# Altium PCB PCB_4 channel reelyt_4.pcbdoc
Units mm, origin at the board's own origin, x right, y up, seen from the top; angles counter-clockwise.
Board outline 162.7 x 82.93 mm, 2 copper layers (Top Layer, Bottom Layer); 40 components, 54 nets, 169 pads, 1 vias.
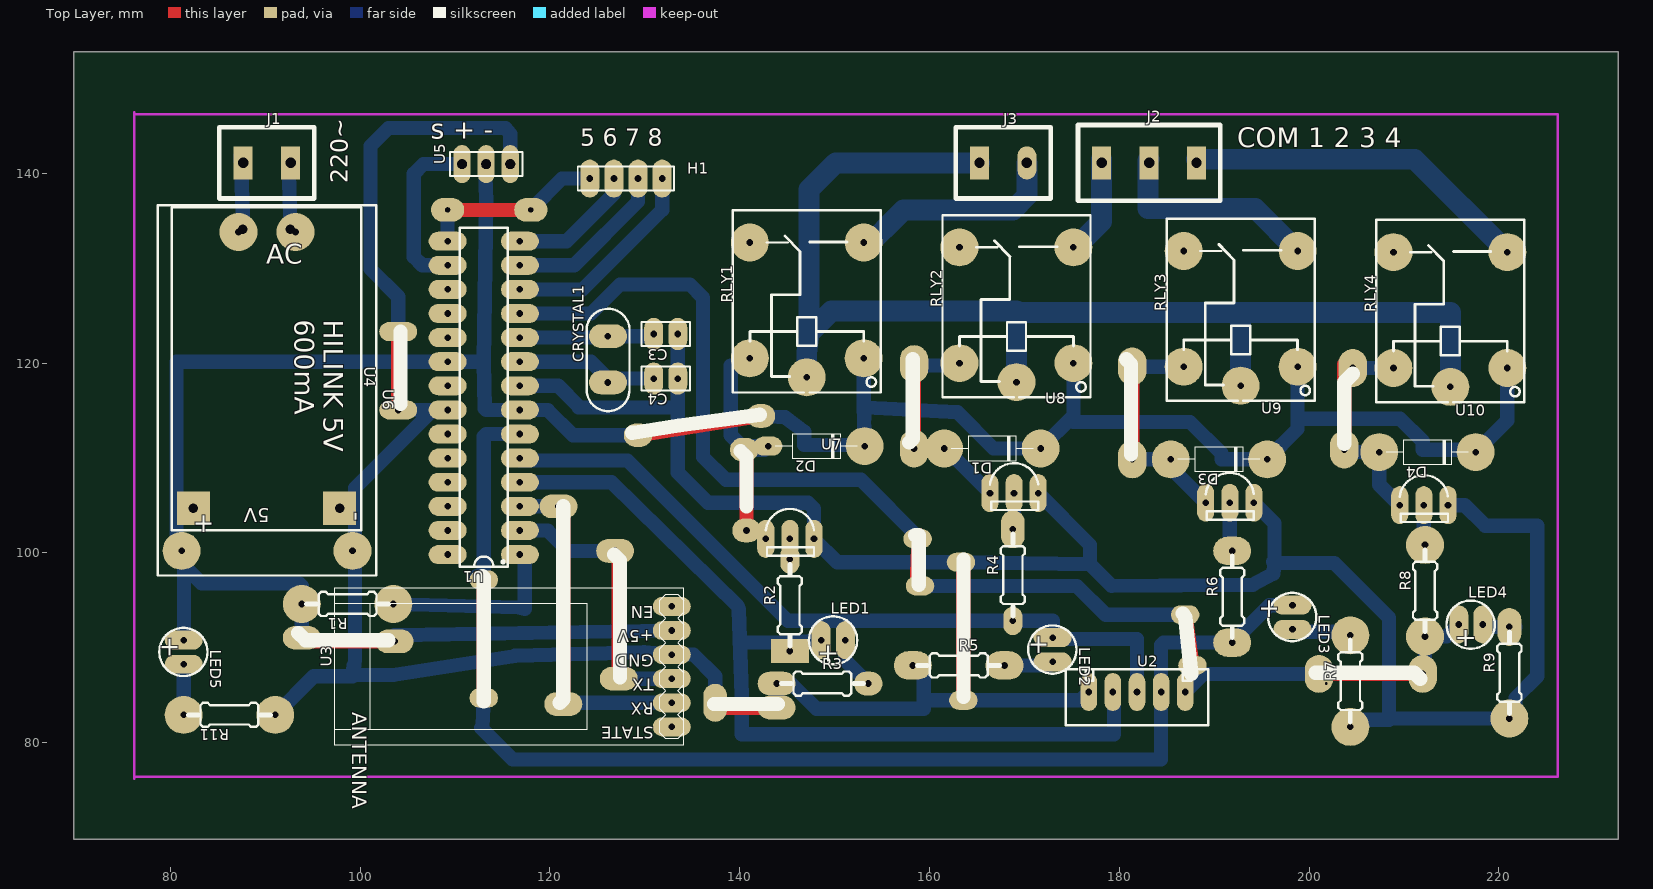
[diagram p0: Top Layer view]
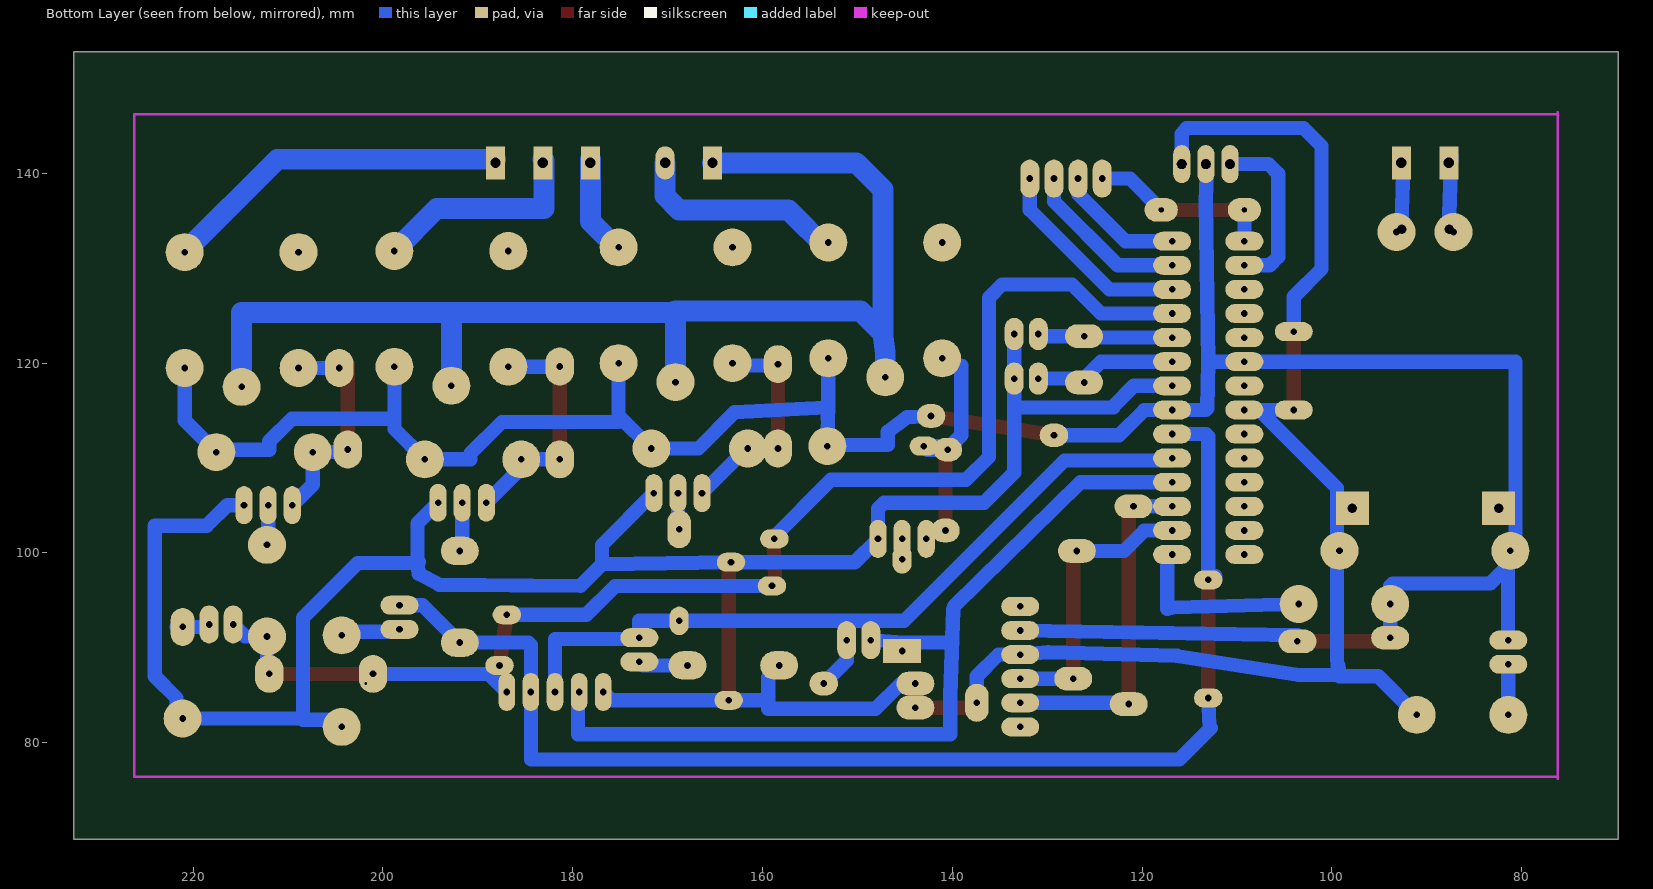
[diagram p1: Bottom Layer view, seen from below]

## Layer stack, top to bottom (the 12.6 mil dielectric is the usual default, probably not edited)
Top Layer: signal copper (thickness not stored)
Dielectric: dielectric 0.32, FR-4, Dk 4.8
Bottom Layer: signal copper (thickness not stored)

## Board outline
232.55,69.85 69.85,69.85 69.85,152.781 232.55,152.781

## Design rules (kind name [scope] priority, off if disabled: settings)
BoardOutlineClearance Default [All] p0: genericclearance=0.254 ignorepadtopadclearanceinfootprint=FALSE except(0: Region-CutoutEdge Arc-SplitContinuation Track-SplitContinuation SMDPad-SplitContinuation THPad-SplitContinuation Via-SplitContinuation Fill-SplitContinuation Poly-SplitContinuation Region-SplitContinuation Text-SplitContinuation; 0.399: Track-OutlineEdge SMDPad-OutlineEdge THPad-OutlineEdge Via-OutlineEdge Fill-OutlineEdge Region-OutlineEdge Poly-OutlineEdge Text-OutlineEdge Sheet-OutlineEdge Hole-OutlineEdge Track-CutoutEdge SMDPad-CutoutEdge THPad-CutoutEdge Via-CutoutEdge Fill-CutoutEdge Poly-CutoutEdge Text-CutoutEdge Sheet-CutoutEdge Hole-CutoutEdge)
Clearance Default [All] p1: gap=0.178 ignorepadtopadclearanceinfootprint=FALSE except(0: Region-Region; 0.399: Track-Track SMDPad-Track THPad-Track Via-Track Fill-Track Region-Track Poly-Track Text-Track Sheet-Track Hole-Track Track-SMDPad SMDPad-SMDPad THPad-SMDPad Via-SMDPad Fill-SMDPad Region-SMDPad Poly-SMDPad Text-SMDPad Sheet-SMDPad Hole-SMDPad Track-THPad SMDPad-THPad THPad-THPad Via-THPad Fill-THPad Region-THPad Poly-THPad Text-THPad Sheet-THPad Hole-THPad Track-Via SMDPad-Via THPad-Via Via-Via Fill-Via Region-Via Poly-Via Text-Via Sheet-Via Hole-Via Track-Fill SMDPad-Fill THPad-Fill Via-Fill Fill-Fill Region-Fill Poly-Fill Text-Fill Sheet-Fill Hole-Fill Track-Region SMDPad-Region THPad-Region Via-Region Fill-Region Poly-Region Text-Region Sheet-Region Hole-Region Track-Poly SMDPad-Poly THPad-Poly Via-Poly Fill-Poly Region-Poly Poly-Poly Text-Poly Sheet-Poly Hole-Poly Track-Text SMDPad-Text THPad-Text Via-Text Fill-Text Region-Text Poly-Text Text-Text Sheet-Text Hole-Text Track-Sheet SMDPad-Sheet THPad-Sheet Via-Sheet Fill-Sheet Region-Sheet Poly-Sheet Text-Sheet Sheet-Sheet Hole-Sheet Track-Hole SMDPad-Hole THPad-Hole Via-Hole Fill-Hole Region-Hole Poly-Hole Text-Hole Sheet-Hole Hole-Hole)
PasteMaskExpansion Common [All] p1: expansion=0
PlaneConnect Default [All] p1: planeconnectstyle=Relief reliefexpansion=0.508 reliefentries=4 reliefconductorwidth=0 reliefairgap=0.025
PolygonConnect Default [All] p1: connectstyle=Relief reliefentries=4 reliefconductorwidth=0 polygonreliefangle="90 Angle" airgapwidth=10
RoutingVias Default [All] p1: viastyle="Through Hole" holewidth=12.008000000000001 minholewidth=12.008000000000001 maxholewidth=2362 width=24.016000000000002 minwidth=24.016000000000002 maxwidth=3938
SolderMaskExpansion Common [All] p1: useseparateexpansions=TRUE expansion=2 expansionbottom=2
Width Default [All] p1: maxlimit=1000 minlimit=59 preferedwidth=59

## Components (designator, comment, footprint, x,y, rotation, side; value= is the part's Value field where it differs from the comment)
C3 "22pf" CAP-TH_L5.0-W2.5-P2.54-D0.7 132.207,123.063 r180 top
C4 "22pf" CAP-TH_L5.0-W2.5-P2.54-D0.7 132.207,118.364 r180 top
CRYSTAL1 "mhz" CRYSTAL-TH_L10.8-W4.5-P4.88 126.111,120.396 r90 top
D1 "1N4007" 1N4007#1 166.624,110.998 r180 top
D2 "1N4007" 1N4007#2 148.082,111.252 r180 top
D3 "1N4007" 1N4007#1 190.5,109.855 r180 top
D4 "1N4007" 1N4007#1 212.471,110.617 r180 top
H1 "1X4 header" "HEADER - HEADER-FEMALE-2.54_1X4" 126.746,139.446 r0 top
J1 "2 X 5MM" "PCB MOUNT SCREW TERMINALS - 2 X 5MM"#1 90.17,141.097 r0 top
J2 "3 X 5MM terminal" "PCB MOUNT SCREW TERMINALS - 3 X 5MM" 183.134,141.097 r0 top
J3 "2 X 5MM" "PCB MOUNT SCREW TERMINALS - 2 X 5MM"#2 167.767,141.097 r0 top
LED1 "LED 5MM" LED-5MM-5MM 151.13,88.265 r0 top
LED2 "LED 5MM" LED-5MM-5MM 170.434,88.519 r270 top
LED3 "LED 5MM" LED-5MM-5MM 195.707,91.948 r270 top
LED4 "LED 5MM" LED-5MM-5MM 218.313,89.916 r0 top
LED5 "LED 5MM" LED-5MM-5MM 78.867,88.265 r270 top
R1 "10k" RESISTOR-1/4W#1 98.679,94.615 r180 top
R2 "100e" RESISTOR-1/4W#2 145.288,94.488 r90 top
R3 "220e" RESISTOR-1/4W#3 148.717,86.233 r0 top
R4 "100e" RESISTOR-1/4W#4 168.783,97.663 r90 top
R5 "220e" RESISTOR-1/4W#5 163.068,88.138 r0 top
R6 "100e" RESISTOR-1/4W#6 191.897,95.377 r90 top
R7 "220e" RESISTOR-1/4W#1 204.343,86.487 r90 top
R8 "100e" RESISTOR-1/4W#1 212.217,96.012 r90 top
R9 "220e" RESISTOR-1/4W#7 221.107,87.376 r90 top
R11 "220e" RESISTOR-1/4W#1 86.233,82.931 r180 top
RLY1 "Реле пылесоса 12В" RELAY-TH_SRD-XXVDC-XL-C 147.066,125.603 r90 top
RLY2 "Реле пылесоса 12В" RELAY-TH_SRD-XXVDC-XL-C 169.164,125.095 r90 top
RLY3 "Реле пылесоса 12В" RELAY-TH_SRD-XXVDC-XL-C 192.786,124.714 r90 top
RLY4 "Реле пылесоса 12В" RELAY-TH_SRD-XXVDC-XL-C 214.884,124.587 r90 top
U1 "ATMEGA328 DIP" ATMEGA328P 113.03,116.332 r180 top
U2 "HEADER5" CONN-TH_HEADER5 181.864,85.344 r0 top
U3 "AMG AMGProductions GTIL HC-05 Bluetooth-module" WIRELESS-BLUETOOTH-HC-05 132.842,84.201 r90 top
U4 "HILINK" HILINK 80.137,136.398 r270 top
U5 "HEADER FEMALE 2.54 1X3 COPY" "HEADER - HEADER-FEMALE-2.54_1X3" 110.744,140.97 r90 top
U6 "HILINK 5V corrected" FP_HILINK_5V_1A 91.694,136.017 r270 top
U7 "TRANSISTOR NPN TO-92 (BC548) COPY" "TRANSISTOR NPN TO-92 (BC548)" 145.288,102.235 r0 top
U8 "TRANSISTOR NPN TO-92 (BC548) COPY" "TRANSISTOR NPN TO-92 (BC548)" 168.91,107.061 r0 top
U9 "TRANSISTOR NPN TO-92 (BC548) COPY" "TRANSISTOR NPN TO-92 (BC548)" 191.643,106.045 r0 top
U10 "TRANSISTOR NPN TO-92 (BC548) COPY" "TRANSISTOR NPN TO-92 (BC548)" 212.09,105.791 r0 top

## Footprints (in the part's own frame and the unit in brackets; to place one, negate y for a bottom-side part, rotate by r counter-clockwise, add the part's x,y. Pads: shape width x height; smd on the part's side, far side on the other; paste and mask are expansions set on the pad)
1N4007#1 [mm]
  round 4 hole 0.7: A(5.08,0) K(-5.08,0)
  silkscreen extent -4.32,-1.27 4.32,1.27
1N4007#2 [mm]
  oval 3x2 hole 0.7: A(5.08,0)
  round 4 hole 0.7: K(-5.08,0)
  silkscreen extent -4.32,-1.27 4.32,1.27
ATMEGA328P [mm]
  oval 4x2 hole 0.7: 1(-3.81,16.51) 2(-3.81,13.97) 3(-3.81,11.43) 4(-3.81,8.89) 5(-3.81,6.35) 6(-3.81,3.81) 7(-3.81,1.27) 8(-3.81,-1.27) 9(-3.81,-3.81) 10(-3.81,-6.35) 11(-3.81,-8.89) 12(-3.81,-11.43) 13(-3.81,-13.97) 14(-3.81,-16.51) 15(3.81,-16.51) 16(3.81,-13.97) 17(3.81,-11.43) 18(3.81,-8.89) 19(3.81,-6.35) 20(3.81,-3.81) 21(3.81,-1.27) 22(3.81,1.27) 23(3.81,3.81) 24(3.81,6.35) 25(3.81,8.89) 26(3.81,11.43) 27(3.81,13.97) 28(3.81,16.51)
  silkscreen extent -2.54,-17.91 2.54,17.78
CAP-TH_L5.0-W2.5-P2.54-D0.7 [mm]
  oval 2x3.4 hole 0.7: 1(-1.27,0) 2(1.27,0)
  silkscreen extent -2.54,-1.27 2.54,1.27
CONN-TH_HEADER5 [mm]
  oval 1.75x4 hole 0.7: 1(-5.08,0) 2(-2.54,0) 3(0,0) 4(2.54,0) 5(5.08,0)
  silkscreen extent -7.5,-3.5 7.5,2.4
CRYSTAL-TH_L10.8-W4.5-P4.88 [mm]
  oval 2.5x4 hole 0.7: 1(-2.44,0) 2(2.44,0)
  silkscreen extent -5.46,-2.28 5.32,2.24
FP_HILINK_5V_1A [mm]
  round 4 hole 0.7: 1(2.2,1.501) 2(2.2,-4.501) 3(35.799,7.501) 4(35.799,-10.5)
  silkscreen extent -0.6,-13 38.4,10
"HEADER - HEADER-FEMALE-2.54_1X3" [mm]
  oval 4x1.8 hole 1.016 slot 1.021 at 0 deg: 1(0,0) 2(0,-2.54) 3(0,-5.08)
  silkscreen extent -1.27,-6.35 1.27,1.27
"HEADER - HEADER-FEMALE-2.54_1X4" [mm]
  oval 2x4 hole 0.7: 1(-2.54,0) 2(0,0) 3(2.54,0) 4(5.08,0)
  silkscreen extent -3.81,-1.27 6.35,1.27
HILINK [mm]
  round 2 hole 1: 1(2.3,12.5) 2(2.3,7.5)
  rect 3.5x3.5 hole 1: 3(31.7,17.7) 4(31.7,2.3)
  silkscreen extent 0,0 34,20
LED-5MM-5MM [mm]
  oval 2x4 hole 0.7: 1(-2.54,2.54) 2(0,2.54)
  silkscreen extent -3.83,-0.02 1.25,5.05
"PCB MOUNT SCREW TERMINALS - 2 X 5MM"#1 [mm]
  rect 2x3.5 hole 1.1: 1(-2.5,0) 2(2.5,0)
  silkscreen extent -5,-3.75 5,3.75
"PCB MOUNT SCREW TERMINALS - 2 X 5MM"#2 [mm]
  rect 2x3.5 hole 1.1: 1(-2.5,0)
  oval 2x3.5 hole 1.1: 2(2.5,0)
  silkscreen extent -5,-3.75 5,3.75
"PCB MOUNT SCREW TERMINALS - 3 X 5MM" [mm]
  rect 2x3.5 hole 1.1: 1(-5,0) 2(0,0) 3(5,0)
  silkscreen extent -7.5,-4 7.5,4
RELAY-TH_SRD-XXVDC-XL-C [mm]
  round 4 hole 0.7: 1(-5.1,-6) 2(7.1,-5.999) 3(7.1,5.999) 4(-5.1,6) 5(-7.1,0)
  silkscreen extent -8.7,-7.8 10.5,7.8
RESISTOR-1/4W#1 [mm]
  round 4 hole 0.7: 1(-4.826,0) 2(4.826,0)
  silkscreen extent -4.32,-1.27 4.32,1.27
RESISTOR-1/4W#2 [mm]
  rect 2.5x4 hole 0.7: 1(-4.826,0)
  oval 3x2 hole 0.7: 2(4.826,0)
  silkscreen extent -4.32,-1.27 4.32,1.27
RESISTOR-1/4W#3 [mm]
  oval 4x2.5 hole 0.7: 1(-4.826,0)
  oval 3x2.5 hole 0.7: 2(4.826,0)
  silkscreen extent -4.32,-1.27 4.32,1.27
RESISTOR-1/4W#4 [mm]
  oval 3x2 hole 0.7: 1(-4.826,0)
  oval 4x2.5 hole 0.7: 2(4.826,0)
  silkscreen extent -4.32,-1.27 4.32,1.27
RESISTOR-1/4W#5 [mm]
  oval 4x3 hole 0.7: 1(-4.826,0) 2(4.826,0)
  silkscreen extent -4.32,-1.27 4.32,1.27
RESISTOR-1/4W#6 [mm]
  oval 3x4 hole 0.7: 1(-4.826,0) 2(4.826,0)
  silkscreen extent -4.32,-1.27 4.32,1.27
RESISTOR-1/4W#7 [mm]
  round 4 hole 0.7: 1(-4.826,0)
  oval 4x2.5 hole 0.7: 2(4.826,0)
  silkscreen extent -4.32,-1.27 4.32,1.27
"TRANSISTOR NPN TO-92 (BC548)" [mm]
  oval 1.8x4 hole 0.7: 1(-2.54,-0.762) 2(0,-0.762) 3(2.54,-0.762)
  silkscreen extent -2.54,-2.54 2.54,2.39
WIRELESS-BLUETOOTH-HC-05 [mm]
  oval 2x4 hole 0.7: 1(-2.54,0) 2(0,0) 3(2.54,0) 4(5.08,0) 5(7.62,0) 6(10.16,0)
  silkscreen extent -4.45,-1.27 12.06,35.56

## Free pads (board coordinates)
  oval 4x2.5 hole 0.7: 2(126.873,100.203) 3(93.853,91.059) 3(127.254,86.741) 4(103.632,90.678) 4(143.891,83.693) 5(121.412,84.074) 6(120.904,104.902)
  oval 3x2 hole 0.7: 2(158.75,101.473) 3(159.004,96.52) 4(186.944,93.472) 5(187.706,88.138) 6(163.312,99.02) 7(163.563,84.468) 8(113.03,97.155) 10(113.03,84.709)
  oval 3x4 hole 0.7: 2(211.963,87.249) 4(201.041,87.249) 5(158.369,110.998) 6(158.369,119.888) 8(181.356,109.855) 10(204.597,119.487) 11(181.356,119.634) 12(203.708,110.891)
  oval 2.5x4 hole 0.7: 5(137.414,84.201)
  oval 3x2.5 hole 0.7: 5(140.462,110.871) 6(140.716,102.362) 7(129.286,112.395) 8(142.24,114.427)
  oval 4x2 hole 0.7: 6(104.013,123.317) 9(104.013,115.062)
  oval 3.5x2.5 hole 0.5 slot 0.525 at 0 deg: 13(109.22,136.144) 14(117.983,136.144)

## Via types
v1: diameter 0.62, hole 0.31, Top Layer to Bottom Layer, 1 vias

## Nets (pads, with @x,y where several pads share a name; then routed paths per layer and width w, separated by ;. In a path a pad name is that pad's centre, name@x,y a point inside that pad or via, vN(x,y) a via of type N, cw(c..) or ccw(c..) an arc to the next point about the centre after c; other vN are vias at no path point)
1: LED1.1 R2.1 U1.4 U2.2 | length 95.5
  Bottom Layer w1.5: U1.4 126.497,107.442 139.827,94.361 ; 139.893,94.056 140.208,84.963 140.208,80.899 179.451,80.899 179.451,85.217 U2.2 ; 140.144,90.551 R2.1@145.161,90.551 ; LED1.1 R2.1@145.161,90.551 ; R2.1@145.161,90.551 145.161,89.662 R2.1@145.161,90.551
2: LED2.1 R4.1 U1.5 U2.3 | length 79.4
  Bottom Layer w1.5: U1.5@116.84,109.728 128.189,109.728 143.937,93.98 145.08,92.837 R4.1 172.974,92.837 LED2.1 173.101,90.932 181.864,90.932 U2.3
3: LED3.1 pad.8@113.03,97.155 pad.10@113.03,84.709 R6.1 U1.6 U2.4 | length 136.5
  Top Layer w1.5: pad.10@113.03,84.709 pad.8@113.03,97.155
  Bottom Layer w1.5: pad.8@112.268,97.536 112.649,97.536 113.03,97.155 113.03,112.268 113.284,112.522 U1.6 ; pad.10@113.03,84.709 112.903,81.661 112.776,81.534 116.078,78.232 184.404,78.232 U2.4 ; U2.4@184.478,85.141 184.478,85.27 U2.4 ; LED3.1 195.834,94.488 R6.1 184.658,90.551 184.404,90.297 U2.4
4: LED4.1 pad.2@158.75,101.473 pad.2@211.963,87.249 pad.4@201.041,87.249 pad.5@187.706,88.138 R8.1 U1.11 U2.5 | length 112.6
  Top Layer w1.5: 158.623,96.456 pad.2@158.877,101.854 ; 186.944,93.472 pad.5@187.706,88.138 ; pad.4@201.041,87.249 pad.2@211.963,87.249
  Bottom Layer w1.5: U1.11@117.094,125.222 124.333,125.222 127.381,128.27 134.747,128.27 136.144,126.873 136.144,114.427 ; 136.144,115.062 136.144,110.109 138.557,107.696 152.781,107.696 pad.2@159.004,101.473 ; pad.5@187.706,88.138 187.706,86.106 U2.5 188.849,87.249 pad.4@201.041,87.249 ; pad.2@211.963,87.249 212.217,87.503 R8.1 214.503,91.186 LED4.1
  other v1: 201.803,86.233
+_1: U6.2 | length 8.1
  Bottom Layer w1.5: 87.416,141.859 87.681,134.051 U6.2@87.447,133.817
+_2: U6.1 | length 8.4
  Bottom Layer w1.5: 92.416,141.859 92.659,134.607 U6.1@93.449,133.817
CRYSTAL1_1: C4.2 CRYSTAL1.1 U1.9 | length 15.2
  Bottom Layer w1.5: U1.9 124.333,120.142 CRYSTAL1.1@126.111,118.364 ; CRYSTAL1.1 CRYSTAL1.1@126.111,118.364 ; C4.2 CRYSTAL1.1@126.111,118.364
CRYSTAL1_2: C3.2 CRYSTAL1.2 U1.10 | length 14.3
  Bottom Layer w1.5: U1.10 125.957,122.682 CRYSTAL1.2 130.71,122.836 C3.2
D2_A: D2.A pad.5@140.462,110.871 pad.6@140.716,102.362 RLY1.4 U7.1 | length 24.7
  Top Layer w1.5: pad.5@140.462,110.871 140.716,110.871 pad.6@140.716,102.87
  Bottom Layer w1.5: pad.5@140.462,110.871 142.621,110.871 D2.A 140.208,111.252 139.065,112.395 139.065,119.741 RLY1.4@141.067,119.741
GND: C3.1 C4.1 pad.4@143.891,83.693 pad.5@137.414,84.201 pad.6@104.013,123.317 pad.6@163.312,99.02 pad.7@163.563,84.468 pad.9 R3.1 R5.1 R7.1 R9.1 R11.1 U1.8 U1.22 U2.1 U3.4 U5.3 U6.3 U7.3 U8.3 U9.3 U10.3 | length 395.7
  Top Layer w1.5: pad.9 pad.6@104.013,123.317 ; pad.5@137.414,84.201 137.414,83.693 pad.4@143.891,83.693 ; pad.6@163.312,99.02 163.563,98.768 pad.7@163.563,84.468
  Bottom Layer w1.5: R11.1 95.123,86.995 99.187,86.995 ; 99.314,87.122 99.449,88.781 99.449,100.218 99.449,106.834 107.676,115.062 U1.22 104.775,115.062 pad.9 ; 99.314,88.138 99.187,87.122 103.505,87.122 116.332,89.154 129.921,89.535 U3.4 135.128,89.281 137.414,86.995 pad.5@137.414,84.201 ; pad.6@104.14,123.317 104.013,123.317 104.013,127 101.092,129.921 101.092,142.875 102.997,144.78 115.316,144.78 115.824,144.145 U5.3 ; U1.8 120.874,117.602 123.017,115.458 ; 123.016,115.316 133.477,115.316 ; C3.1 C4.1 133.477,108.458 136.652,105.283 147.193,105.283 147.828,104.648 U7.3 150.281,99.02 163.312,99.02 176.906,98.811 179.197,96.52 194.056,96.647 196.215,97.79 196.342,98.933 ; pad.4@143.891,83.693 R3.1 145.415,86.233 148.082,83.566 159.385,83.566 159.385,84.467 R5.1@159.385,86.868 ; 159.385,84.468 163.563,84.468 175.908,84.468 U2.1 ; U8.3 176.905,100.844 176.905,98.81 ; U9.3 196.342,103.124 196.342,98.925 196.215,99.06 ; 196.342,99.839 196.342,98.933 ; R7.1@205.232,82.042 205.613,82.423 208.407,82.423 ; U10.3 216.408,105.029 218.567,102.87 224.028,102.87 224.028,86.995 221.742,84.709 221.742,82.55 208.534,82.55 208.407,82.423 ; 196.342,98.933 202.641,98.933 208.407,93.167 208.407,82.423
IR: U1.16 U5.1 | length 18.2
  Bottom Layer w1.5: U1.16 106.553,130.302 105.664,131.191 105.664,139.954 106.68,140.97 U5.1
LED2_2: LED2.2 R5.2 | length 5.2
  Bottom Layer w1.5: R5.2 172.593,88.138 LED2.2
LED3_2: LED3.2 R7.2 | length 7.1
  Bottom Layer w1.5: LED3.2 198.501,91.694 R7.2@205.232,91.694
LED4_2: LED4.2 R9.2 | length 3.5
  Bottom Layer w1.5: LED4.2 218.567,92.202 R9.2@221.742,92.202
LED5_2: LED5.2 R11.2 | length 5.3
  Bottom Layer w1.5: R11.2 LED5.2
R1_1: R1.1 U1.1 | length 19.8
  Bottom Layer w1.5: R1.1 116.713,94.234 117.348,94.107 117.348,99.314 U1.1
R2_2: R2.2 U7.2
R3_2: LED1.2 R3.2 | length 5.6
  Bottom Layer w1.5: LED1.2 151.13,88.646 R3.2
R4_2: R4.2 U8.2 | length 3.9
  Bottom Layer w1.5: R4.2 168.91,102.616 U8.2
R6_2: R6.2 U9.2 | length 5.2
  Bottom Layer w1.5: U9.2 191.643,100.457 R6.2
R8_2: R8.2 U10.2 | length 4.2
  Bottom Layer w1.5: U10.2 212.09,100.965 R8.2
RLY1_2: J3.2 RLY1.2 | length 23
  Bottom Layer w2.2: RLY1.2@153.065,131.94 157.269,136.144 168.783,136.144 170.266,137.627 J3.2
RLY1_5: J3.1 RLY1.5 RLY2.5 RLY3.5 RLY4.5 | length 138.6
  Bottom Layer w1.5: RLY2.5@169.164,117.741 RLY2.5@169.164,118.335
  Bottom Layer w2.2: RLY1.5@147.066,117.741 147.066,121.099 147.32,123.126 ; 147.32,123.063 147.32,123.126 ; J3.1 150.114,141.097 147.32,138.303 147.32,123.126 ; RLY3.5 192.786,125.349 ; RLY4.5 214.884,118.059 214.884,125.349 214.757,125.349 169.164,125.349 169.164,118.336 169.164,125.476 149.669,125.476 147.32,123.126
RLY2_2: J2.1 RLY2.2 | length 10.8
  Bottom Layer w2.2: RLY2.2@175.164,131.941 178.134,134.912 J2.1@178.134,141.478
RLY2_4: D1.A pad.5@158.369,110.998 pad.6@158.369,119.888 RLY2.4 U8.1 | length 24.2
  Top Layer w1.5: pad.5@158.369,110.998 pad.6@158.369,119.888
  Bottom Layer w1.5: pad.5@157.988,111.379 158.369,110.998 D1.A 161.671,110.998 U8.1 ; pad.6@158.369,119.741 RLY2.4@163.164,119.741
RLY3_2: J2.2 RLY3.2 | length 22.9
  Bottom Layer w2.2: J2.2@183.134,141.478 183.007,141.351 183.007,136.271 194.328,136.271 RLY3.2
RLY3_4: D3.A pad.8@181.356,109.855 pad.11 RLY3.4 U9.1 | length 25.4
  Top Layer w1.5: pad.8@181.356,109.855 pad.11
  Bottom Layer w1.5: pad.8@181.356,109.855 D3.A 185.42,108.966 U9.1 ; pad.11@181.356,119.614 RLY3.4
RLY4_2: J2.3 RLY4.2 | length 36.8
  Bottom Layer w2.2: J2.3@188.134,141.478 211.092,141.478 RLY4.2
RLY4_4: D4.A pad.10@204.597,119.487 pad.12 RLY4.4 U10.1 | length 24
  Top Layer w1.5: pad.12 pad.10@203.708,119.888
  Bottom Layer w1.5: pad.12@204.089,110.617 D4.A 207.391,107.188 U10.1 ; pad.10@204.597,119.487 RLY4.4 RLY4.4@209.55,118.821
RX: pad.5@121.412,84.074 pad.6@120.904,104.902 U1.3 U3.2 | length 36.7
  Top Layer w1.5: pad.6@120.904,104.902 121.412,104.394 pad.5@121.412,84.074
  Bottom Layer w1.5: U1.3 pad.6@120.904,104.902 ; pad.5@121.412,84.074 121.412,84.201 U3.2
S$23988: pad.3@159.004,96.52 pad.4@186.944,93.472 | length 29.2
  Bottom Layer w1.5: pad.3@159.004,96.52 175.514,96.52 178.562,93.472 pad.4@186.944,93.472
S$24136: 
S$24140: 
S$24144: 
S$24148: 
S$24152: 
S$24156: 
S$24160: 
S$24164: 
S$24320: 
S$24774: 
S$24781: 
S$24875: 
S$24960: 
S$24967: 
S$25226: 
TX: pad.2@126.873,100.203 pad.3@127.254,86.741 U1.2 U3.3 | length 30.1
  Top Layer w1.5: pad.2@126.873,100.203 127.254,99.822 pad.3@127.254,86.741
  Bottom Layer w1.5: U1.2 119.761,102.362 121.92,100.203 pad.2@126.873,100.203 ; pad.3@127.254,86.741 U3.3
U1_12: H1.4 U1.12 | length 21.8
  Bottom Layer w1.5: U1.12 123.444,127.762 131.826,136.144 H1.4
U1_13: H1.3 U1.13 | length 17.6
  Bottom Layer w1.5: U1.13 122.555,130.302 129.286,137.033 H1.3
U1_14: H1.2 U1.14 | length 13.6
  Bottom Layer w1.5: U1.14 121.743,132.842 126.746,137.845 H1.2
U1_15: H1.1 pad.13 pad.14 U1.15 | length 20.3
  Top Layer w1.5: pad.13 pad.14
  Bottom Layer w1.5: U1.15 pad.13 109.474,135.89 pad.13@109.474,135.636 ; pad.14 121.285,139.446 H1.1
U6_1: J1.1
U6_2: J1.2
VCC: D1.K D2.K D3.K D4.K LED5.1 pad.3@93.853,91.059 pad.4@103.632,90.678 pad.7@129.286,112.395 pad.8@142.24,114.427 R1.2 RLY1.1 RLY2.1 RLY3.1 RLY4.1 U1.7 U1.20 U3.5 U5.2 U6.4 | length 300.3
  Top Layer w1.5: pad.3@93.853,91.059 94.234,90.678 pad.4@103.632,90.678 ; pad.7@129.286,112.395 pad.8@142.24,114.427
  Bottom Layer w1.5: U6.4@80.94,101.615 80.94,99.146 83.312,96.774 93.599,96.774 93.853,96.52 pad.3@93.853,91.694 ; LED5.1 81.448,90.846 81.448,100.218 80.645,100.218 80.645,120.142 U1.20 ; pad.4@103.632,91.313 U3.5 ; 112.522,120.142 U1.20 ; U5.2 113.157,140.97 113.284,137.033 113.03,120.142 ; U1.7@115.14,115.062 U1.7 119.761,115.062 122.428,112.395 pad.7@129.286,112.395 ; U1.7@115.141,115.062 113.284,115.062 113.137,115.209 113.03,120.142 ; pad.8@142.24,114.427 144.78,114.3 146.812,112.776 146.812,111.379 153.035,111.379 D2.K 153.066,115.818 ; RLY1.1@153.066,119.741 153.066,115.818 ; 153.111,114.173 153.066,115.818 ; 153.289,115.316 162.941,114.808 166.751,110.998 D1.K 175.164,114.458 RLY2.1@175.164,119.741 ; 175.164,113.792 187.452,113.792 190.754,110.49 190.754,109.855 D3.K 198.786,113.061 RLY3.1 ; 198.785,114.14 209.583,114.14 211.963,111.76 211.963,110.871 217.297,110.871 D4.K 220.884,113.95 RLY4.1 ; U1.20 110.861,120.142 113.03,120.142
pads on no net: RLY1.3 RLY2.3 RLY3.3 RLY4.3 U1.17 U1.18 U1.19 U1.21 U1.23 U1.24 U1.25 U1.26 U1.27 U1.28 U3.1 U3.6 U4.1 U4.2 U4.3 U4.4

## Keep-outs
Board Outline Layer:
  lines w0.254: 76.2,76.2 76.2,146.2 ; 76.2,76.431 226.2,76.431 226.2,146.2 76.2,146.2 ; 76.2,146.431 76.2,146.2

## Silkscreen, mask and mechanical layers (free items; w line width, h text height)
Top Silkscreen Layer:
  lines w1.5 net S$24136: 186.69,93.599 186.944,93.218 187.579,87.249
  lines w1.5 net S$24140: 158.496,101.854 158.877,101.854 158.877,96.647
  lines w1.5 net S$24144: 121.031,84.201 121.412,84.582 121.412,104.902
  lines w1.5 net S$24148: 93.472,91.567 94.234,90.805 102.997,90.805
  lines w1.5 net S$24152: 157.861,111.633 158.242,112.014 158.242,120.396
  lines w1.5 net S$24156: 180.721,120.396 181.229,119.888 181.229,110.363
  lines w1.5 net S$24160: 203.708,111.506 203.708,117.983 204.597,118.872
  lines w1.5 net S$24164: 200.66,87.376 211.074,87.376 211.709,86.741
  lines w1.5 net S$24320: 163.576,84.836 163.576,99.314
  lines w1.5 net S$24774: 128.651,112.649 133.604,113.411 142.113,114.554
  lines w1.5 net S$24781: 112.903,97.536 113.03,97.409 113.03,84.328
  lines w1.5 net S$24875: 126.746,99.822 127.381,99.187 127.381,86.868
  lines w1.5 net S$24960: 137.287,84.074 144.018,84.074
  lines w1.5 net S$24967: 140.081,110.744 140.716,110.109 140.716,104.902
  lines w1.5 net S$25226: 104.267,115.697 104.267,123.317
  text "s + -" at 107.442,143.637 h2.03
  text "5 6 7 8" at 123.19,142.875 h1.8
  text "COM 1 2 3 4" at 192.405,142.748 h2.03
  text "220~" at 98.679,138.938 h1.8 r90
